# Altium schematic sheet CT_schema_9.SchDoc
size 274 x 160 mm
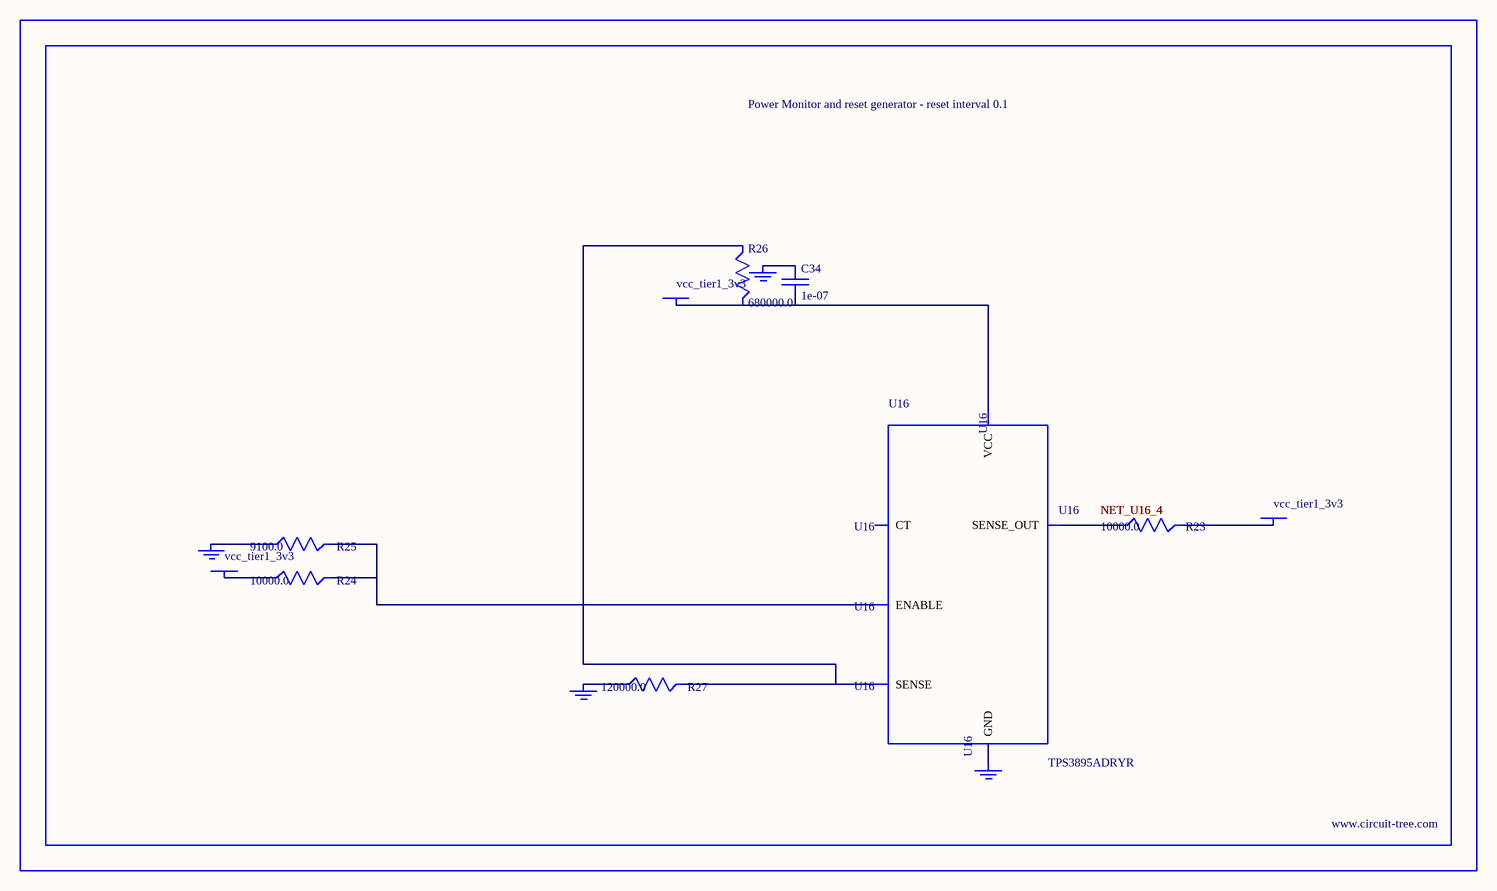
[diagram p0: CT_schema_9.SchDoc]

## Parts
BORDER8  (no value)
C34  1e-07  [C0402]
GND_INSTANCE_8_0  (no value)
GND_INSTANCE_8_1  (no value)
GND_INSTANCE_8_2  (no value)
GND_INSTANCE_8_3  (no value)
POWER_INSTANCE_8_0  vcc_tier1_3v3
POWER_INSTANCE_8_1  vcc_tier1_3v3
POWER_INSTANCE_8_2  vcc_tier1_3v3
R23  10000.0  [R0603]
R24  10000.0  [R0603]
R25  9100.0  [R0603]
R26  680000.0  [R0603]
R27  120000.0  [R0603]
U16  TPS3895ADRYR  [SON-6]

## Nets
NetC34_1: C34.1 GND_INSTANCE_8_2.0(GND)
NetC34_2: C34.2 POWER_INSTANCE_8_2.0(PWR) R26.2 U16.6(VCC)
NetGND_INSTANCE_8_0_0: GND_INSTANCE_8_0.0(GND) R25.1
NetGND_INSTANCE_8_1_0: GND_INSTANCE_8_1.0(GND) R27.1
NetGND_INSTANCE_8_3_0: GND_INSTANCE_8_3.0(GND) U16.2(GND)
NetPOWER_INSTANCE_8_0_0: POWER_INSTANCE_8_0.0(PWR) R24.1
NetPOWER_INSTANCE_8_1_0: POWER_INSTANCE_8_1.0(PWR) R23.2
NetR23_1: R23.1 U16.4(SENSE_OUT)
NetR24_2: R24.2 R25.2 U16.1(ENABLE)
NetR26_1: R26.1 R27.2 U16.3(SENSE)

Not connected (* = marked no-connect by the designer): U16 5(CT)

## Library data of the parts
BORDER8 = BORDER_PAGE8
C34 = C0402C104K3RACTU
GND_INSTANCE_8_0-GND_INSTANCE_8_3 = GND
POWER_INSTANCE_8_0-POWER_INSTANCE_8_2 = PWR
R23 R24 = RC0603JR-0710KL
R25 = RC0603JR-079K1L
R26 = RC0603JR-07680KL
R27 = RC0603JR-07120KL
